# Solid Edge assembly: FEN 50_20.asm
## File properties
Title: Zylinder
Author: bmolnar
Template: iso assembly.asm
Last saved by: bmolnar
Revision: 13
Application: Solid Edge
Username: bmolnar
Dokumentum tartalom típus: 1
Document Number: FEN 50/20
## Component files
Kit_1.par
Profilrohr.par
Kit_2.par
Kolbenstange.par
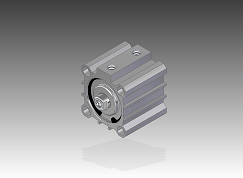
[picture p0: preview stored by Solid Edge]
